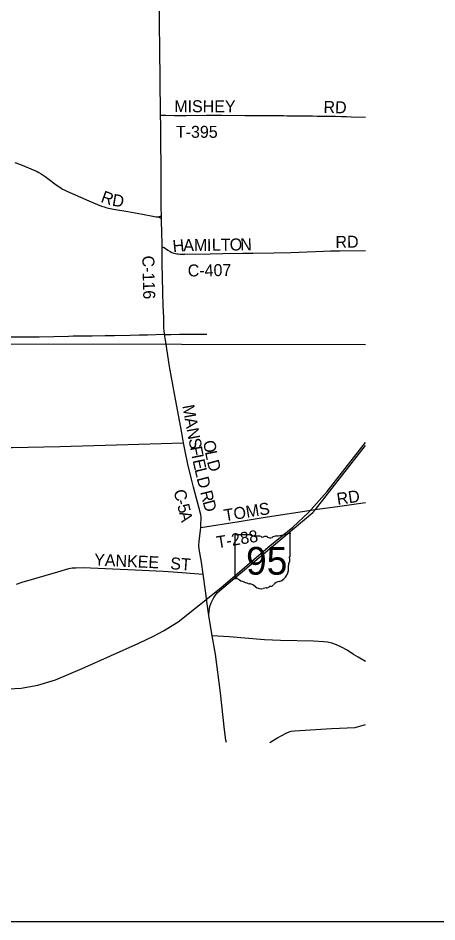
# Model space of a CAD drawing. Extents: x 40529 to 41139, y 15164 to 15584.
# Drawn here: x 40688.2 to 40747.9, y 15164.3 to 15293.1 of the extents above; entities that cross this region are included whole.
import ezdxf

# ---------------------------------------------------------------- set-up
doc = ezdxf.new("R2010")
doc.units = 0
for name, color, linetype in [('GM_X_County_Road', 7, 'Continuous'), ('GM_X_County_Road_Text', 7, 'Continuous'), ('GM_X_Rail_Line', 7, 'Continuous'), ('GM_X_State_Route', 7, 'Continuous'), ('GM_X_State_Shield', 7, 'Continuous'), ('GM_X_Township_Road', 7, 'Continuous'), ('GM_X_Township_Road_Text', 7, 'Continuous'), ('SC_Scratch1', 7, 'Continuous'), ('SH_Cut_Line', 7, 'Continuous')]:
    doc.layers.add(name, color=color, linetype=linetype)

msp = doc.modelspace()

# ---------------------------------------------------------------- linework, layer by layer
at = {"layer": 'GM_X_County_Road'}
msp.add_line((40708.6, 15264.51), (40708.59, 15264.99), dxfattribs=at)
for points in [[(40708.47, 15279.32), (40708.45, 15279.8), (40708.45, 15280.02), (40708.44, 15280.23), (40708.44, 15280.51), (40708.42, 15283.4), (40708.42, 15283.96), (40708.42, 15284.62), (40708.41, 15286.02), (40708.38, 15287.08), (40708.34, 15289.41), (40708.34, 15289.95), (40708.34, 15290.3), (40708.33, 15290.78), (40708.31, 15291.87), (40708.32, 15292.45), (40708.33, 15294.12), (40708.32, 15294.22)], [(40708.59, 15264.99), (40708.56, 15266.15), (40708.53, 15268.47), (40708.53, 15270.06), (40708.53, 15271.08), (40708.53, 15272.39), (40708.53, 15273.13), (40708.52, 15274.34), (40708.52, 15276.3), (40708.52, 15276.95), (40708.51, 15277.12), (40708.51, 15277.95), (40708.47, 15279.25), (40708.47, 15279.32)], [(40687.71, 15272.58), (40688.49, 15272.27), (40690.55, 15271.41), (40690.89, 15271.26), (40691.14, 15271.12), (40691.45, 15270.93), (40692, 15270.57), (40692.61, 15270.14), (40693.42, 15269.53), (40694.03, 15269.08), (40694.26, 15268.93), (40694.5, 15268.78), (40694.75, 15268.65), (40695.09, 15268.49), (40695.85, 15268.15), (40698.24, 15267.09), (40698.93, 15266.81), (40700.05, 15266.36), (40700.41, 15266.23), (40700.68, 15266.16), (40701.04, 15266.07), (40701.77, 15265.93), (40703.79, 15265.57), (40705.9, 15265.2), (40707.36, 15264.91), (40707.82, 15264.82), (40708.01, 15264.8), (40708.14, 15264.8)], [(40708.14, 15264.8), (40708.3, 15264.84), (40708.47, 15264.93), (40708.59, 15264.99)], [(40708.14, 15264.8), (40708.39, 15264.68), (40708.5, 15264.59), (40708.6, 15264.51)], [(40708.69, 15260.56), (40708.69, 15261.03), (40708.65, 15262.52), (40708.6, 15264.29), (40708.6, 15264.51)], [(40709.04, 15248.07), (40709.03, 15248.11), (40709.01, 15248.22), (40708.99, 15248.49), (40708.94, 15249.13), (40708.91, 15249.97), (40708.91, 15250.43), (40708.86, 15252.2), (40708.81, 15253.97), (40708.74, 15256.3), (40708.71, 15257.97), (40708.71, 15258.71), (40708.7, 15259.45), (40708.7, 15259.82), (40708.69, 15260.56)], [(40708.69, 15260.56), (40708.82, 15260.51), (40708.96, 15260.45), (40709.51, 15260.08), (40709.82, 15259.88), (40710.07, 15259.75), (40710.34, 15259.65), (40710.61, 15259.58), (40710.79, 15259.54), (40710.98, 15259.52), (40711.26, 15259.51), (40711.92, 15259.51), (40715.55, 15259.55), (40717.32, 15259.58), (40720.21, 15259.63), (40721.61, 15259.64), (40724.59, 15259.68), (40727.01, 15259.74), (40728.22, 15259.78), (40731.67, 15259.93), (40732.69, 15259.96), (40734, 15259.97), (40737.65, 15260)], [(40715.36, 15207.97), (40715.09, 15209.67), (40714.87, 15211.51), (40714.54, 15213.86), (40714.3, 15215.58), (40713.97, 15217.44), (40713.91, 15217.98), (40713.98, 15218.55), (40714.17, 15220.16), (40714.22, 15220.52), (40714.22, 15221.11), (40714.27, 15221.69), (40714.23, 15222.05), (40714.21, 15222.32), (40713.9, 15223.45), (40713.15, 15226.27), (40712.89, 15227.42), (40712.36, 15229.57), (40711.99, 15231.42), (40711.73, 15232.62), (40711.49, 15234.02), (40710.89, 15237.3), (40710.35, 15240.1), (40709.75, 15243.46), (40709.24, 15246.96), (40709.04, 15248.07)], [(40687.94, 15212.45), (40688.76, 15212.74), (40693.84, 15214.22), (40695.38, 15214.7), (40695.87, 15214.77), (40696.39, 15214.8), (40697.42, 15214.82), (40704.86, 15214.49), (40708.86, 15214.31), (40710.28, 15214.2), (40714.54, 15213.86)], [(40737.65, 15201.43), (40736.64, 15202.04), (40735.98, 15202.43), (40735.04, 15203.03), (40734.25, 15203.5), (40733.55, 15203.79), (40732.86, 15204.04), (40732.25, 15204.17), (40731.72, 15204.25), (40730.27, 15204.33), (40725.54, 15204.42), (40723.29, 15204.54), (40718.26, 15204.94), (40715.81, 15205.08)], [(40724.06, 15189.89), (40725.05, 15190.49), (40726.45, 15191.25), (40726.8, 15191.42), (40727.1, 15191.52), (40727.54, 15191.57), (40732.81, 15191.87), (40736.21, 15192.04), (40737.65, 15192.46)]]:
    msp.add_lwpolyline(points, dxfattribs=at)
at = {"layer": 'GM_X_Rail_Line'}
msp.add_lwpolyline([(40668.64, 15189.89), (40669.2, 15190.96), (40670.65, 15192.58), (40673.94, 15195.16), (40676.07, 15196.33), (40678.25, 15197.05), (40680.29, 15197.55), (40682.99, 15197.72), (40685.84, 15197.5), (40688.61, 15197.62), (40690.98, 15198.06), (40693.48, 15198.84), (40697.28, 15200.43), (40705.39, 15204.07), (40707.45, 15205.06), (40708.87, 15205.81), (40710.96, 15207.11), (40717.07, 15211.94), (40723.79, 15217.72), (40727.32, 15220.6), (40729.54, 15222.69), (40732.21, 15225.65), (40737.65, 15232.65)], dxfattribs=at)
at = {"layer": 'GM_X_State_Route'}
msp.add_lwpolyline([(40717.84, 15189.89), (40717.78, 15190.21), (40717.58, 15191.68), (40717.02, 15196.95), (40716.28, 15202.49), (40715.81, 15205.08), (40715.36, 15207.97), (40715.39, 15208.64), (40715.48, 15209.25), (40715.66, 15209.8), (40716.04, 15210.56), (40716.53, 15211.2), (40717.19, 15211.81), (40730.19, 15222.67), (40730.54, 15223.11), (40737.65, 15232.21)], dxfattribs=at)
at = {"layer": 'GM_X_State_Shield'}
for p, q in [((40719.05, 15219.39), (40719.05, 15213.38)), ((40721.45, 15219.49), (40719.13, 15219.49)), ((40726.96, 15216.5), (40726.96, 15219.64)), ((40726.96, 15216.5), (40726.96, 15216.5))]:
    msp.add_line(p, q, dxfattribs=at)
for centre, radius, start, end in [((40719.14, 15219.4), 0.0916, 98.1301, 188.1301), ((40722, 15220.19), 0.889, 231.6195, 271.1119), ((40722.29, 15216.12), 3.19, 80.4867, 94.9883), ((40723.02, 15219.43), 0.256, 219.7921, 297.1024), ((40723.4, 15218.74), 0.533, 54.4667, 119.1411), ((40724.08, 15219.69), 0.641, 233.8562, 294.8282), ((40725.22, 15217.66), 1.69, 97.3462, 120.7689), ((40724.15, 15227.67), 8.39, 275.8445, 288.9065), ((40726.88, 15219.65), 0.0881, 351.8621, 97.738), ((40726.87, 15216.49), 0.0942, 289.6038, 7.7341), ((40727.28, 15215.18), 0.595, 136.8065, 186.9296), ((40726.94, 15216.27), 0.136, 107.944, 210.337), ((40726.08, 15215.87), 0.818, 340.033, 23.6496), ((40724.62, 15214.78), 2.1, 292.3089, 8.9858), ((40719.15, 15213.37), 0.0925, 171.9584, 258.3066), ((40719.16, 15213.98), 0.706, 267.339, 280.6039), ((40719.3, 15213.04), 0.254, 29.7484, 93.2717), ((40722.52, 15218.43), 6.06, 240.4129, 257.1985), ((40725.5, 15211.7), 1.15, 94.4031, 142.5768), ((40720.71, 15210.69), 1.9, 47.1842, 75.836), ((40722.76, 15213.01), 1.2, 230.7004, 286.2918), ((40723.45, 15210.93), 0.988, 85.6951, 111.2099), ((40723.54, 15212.56), 0.641, 268.777, 315.5493), ((40724.12, 15211.98), 0.18, 65.7517, 132.6484), ((40724.04, 15212.8), 0.678, 282.8732, 323.2771)]:
    msp.add_arc(centre, radius, start, end, dxfattribs=at)
at = {"layer": 'GM_X_Township_Road'}
for points in [[(40708.47, 15279.32), (40708.61, 15279.31), (40708.94, 15279.3), (40709.24, 15279.29), (40710.43, 15279.28), (40712.1, 15279.27), (40714.98, 15279.29), (40717.21, 15279.29), (40720.49, 15279.26), (40721.96, 15279.25), (40722.34, 15279.25), (40723.55, 15279.24), (40724.19, 15279.25), (40725.27, 15279.25), (40725.97, 15279.24), (40726.5, 15279.23), (40726.66, 15279.22), (40726.88, 15279.21), (40727.28, 15279.2), (40728.76, 15279.19), (40730.14, 15279.19), (40730.79, 15279.18), (40730.98, 15279.18), (40731.97, 15279.18), (40732.19, 15279.17), (40732.28, 15279.17), (40732.47, 15279.17), (40733.4, 15279.16), (40734.24, 15279.12), (40734.97, 15279.11), (40735.63, 15279.09), (40737.65, 15279.03)], [(40685.74, 15247.69), (40686.33, 15247.69), (40688.94, 15247.7), (40691.17, 15247.73), (40695.36, 15247.83), (40696.01, 15247.84), (40696.2, 15247.85), (40697.31, 15247.84), (40698.71, 15247.87), (40700.57, 15247.9), (40701.88, 15247.92), (40704.11, 15247.96), (40705.42, 15247.99), (40706.62, 15248.01), (40708.95, 15248.07), (40709.04, 15248.07)], [(40709.04, 15248.07), (40709.11, 15248.05), (40709.19, 15248.05), (40709.94, 15248.06), (40711.15, 15248.09), (40711.71, 15248.08), (40713.11, 15248.09), (40714.32, 15248.1), (40715.07, 15248.09)], [(40684.82, 15231.93), (40687.33, 15231.95), (40694.11, 15232.1), (40702.2, 15232.34), (40711.73, 15232.62)], [(40714.22, 15220.52), (40719.66, 15221.38), (40723.07, 15221.94), (40730.54, 15223.11), (40730.83, 15223.15)], [(40730.83, 15223.15), (40734.01, 15223.57), (40737.65, 15224.09)]]:
    msp.add_lwpolyline(points, dxfattribs=at)
at = {"layer": 'SC_Scratch1'}
msp.add_lwpolyline([(40528.65, 15584.31), (41138.65, 15584.31), (41138.65, 15164.31), (40528.65, 15164.31)], close=True, dxfattribs=at)
at = {"layer": 'SH_Cut_Line'}
msp.add_line((40533.65, 15247.13), (40737.65, 15246.6), dxfattribs=at)

# ---------------------------------------------------------------- texts
at = {"layer": 'GM_X_County_Road_Text'}
for s, height, rotation, p in [('R', 1.71, 340.174, (40699.84, 15266.98)), ('D', 1.71, 350.4605, (40701.48, 15266.42)), ('H', 1.71, 5.8367, (40710.27, 15259.77)), ('A', 1.71, 0.632, (40711.72, 15259.92)), ('M', 1.71, 0.7151, (40713.23, 15259.94)), ('I', 1.71, 0.7143, (40715.08, 15259.96)), ('L', 1.71, 0.7136, (40715.78, 15259.97)), ('T', 1.71, 0.7136, (40717.06, 15259.99)), ('O', 1.71, 0.714, (40718.33, 15260.01)), ('N', 1.71, 0.714, (40719.83, 15260.02)), ('RD', 1.706, 0.4937, (40733.4, 15260.39)), ('C-116', 1.706, 271.3596, (40705.86, 15259.27)), ('C-407', 1.706, 0.8259, (40712.35, 15256.31)), ('M', 1.71, 280.5389, (40711.55, 15237.88)), ('A', 1.71, 280.5362, (40711.89, 15236.06)), ('N', 1.71, 280.539, (40712.16, 15234.58)), ('S', 1.71, 280.55, (40712.44, 15233.11)), ('F', 1.71, 280.8421, (40712.65, 15231.96)), ('O', 1.71, 280.7177, (40714.51, 15232.8)), ('I', 1.71, 281.5248, (40712.87, 15230.81)), ('L', 1.71, 281.0289, (40714.79, 15231.32)), ('E', 1.71, 282.3921, (40713.02, 15230.1)), ('D', 1.71, 285.1228, (40715.06, 15229.93)), ('L', 1.71, 283.5623, (40713.3, 15228.81)), ('D', 1.71, 284.0754, (40713.6, 15227.56)), ('C', 1.71, 282.851, (40710.32, 15225.76)), ('R', 1.71, 284.1755, (40714.1, 15225.59)), ('-', 1.71, 284.9034, (40710.65, 15224.33)), ('D', 1.71, 284.9981, (40714.45, 15224.2)), ('5', 1.71, 284.8781, (40710.83, 15223.65)), ('A', 1.71, 283.4337, (40711.1, 15222.65)), ('YANKEE', 1.706, 357.3296, (40698.97, 15215.13)), ('ST', 1.706, 355.8721, (40709.8, 15214.6))]:
    msp.add_text(s, height=height, rotation=rotation, dxfattribs=at).set_placement(p)
at = {"layer": 'GM_X_State_Shield'}
msp.add_text('95', height=3.955, dxfattribs=at).set_placement((40720.65, 15213.81))
at = {"layer": 'GM_X_Township_Road_Text'}
for s, rotation, p in [('MISHEY', 359.8207, (40710.41, 15279.74)), ('RD', 358.5186, (40731.67, 15279.64)), ('T-395', 0, (40710.65, 15276.08)), ('RD', 8.4806, (40733.7, 15223.74)), ('TOMS', 9.3009, (40717.63, 15221.4)), ('T-288', 9.2373, (40716.57, 15217.57))]:
    msp.add_text(s, height=1.706, rotation=rotation, dxfattribs=at).set_placement(p)

doc.saveas('drawing.dxf')
